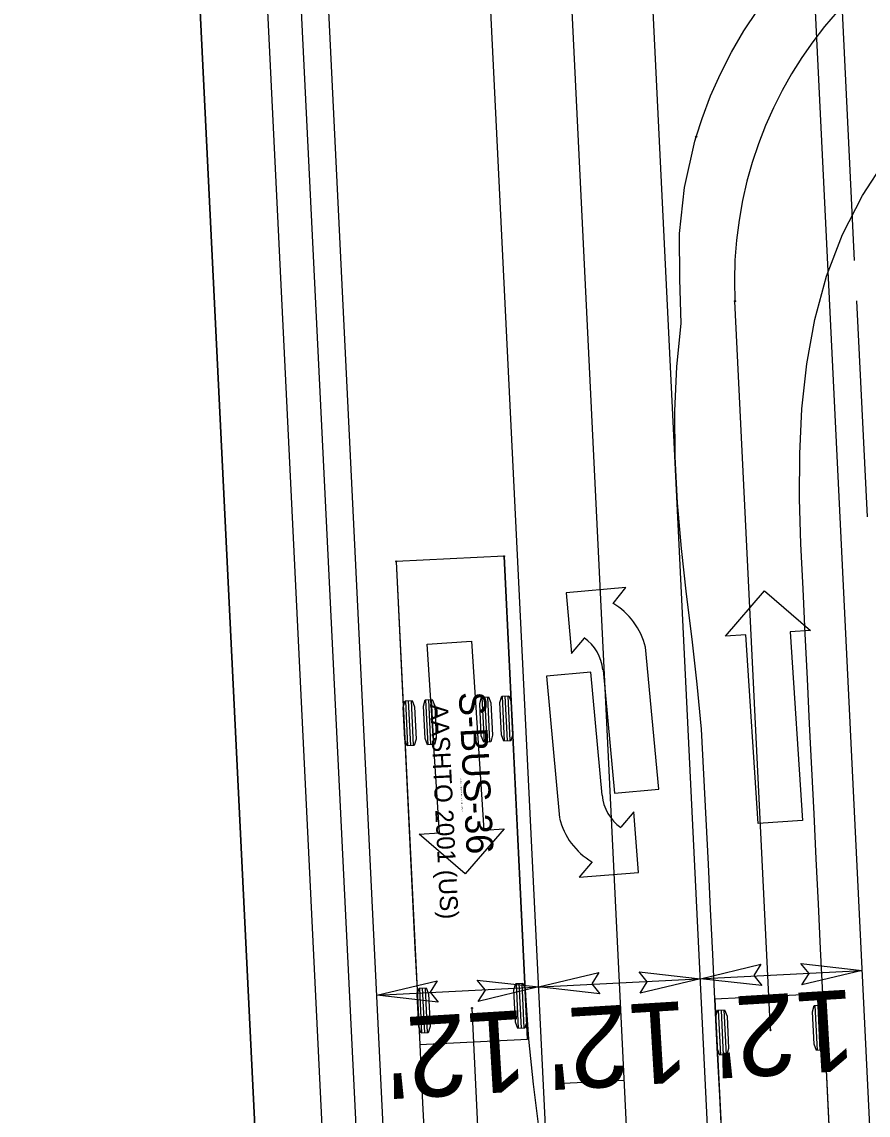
# Model space of a CAD drawing. Extents: x 2367848 to 2369479, y 800728 to 808616.
# Drawn here: x 2368775.2 to 2368837.9, y 804125 to 804206 of the extents above; entities that cross this region are included whole.
import ezdxf

# ---------------------------------------------------------------- set-up
doc = ezdxf.new("R2010")
doc.units = 0
for name, color, linetype in [('Prop AutoTurn Projected Path', 7, 'Continuous'), ('Prop AutoTurn Simulation', 7, 'Continuous'), ('Prop Conc 2ft 6in Curb and Gutter', 7, 'Continuous'), ('Prop Conc 4in Sidewalk', 7, 'Continuous'), ('Prop Conc Drive Radius Type', 7, 'Continuous'), ('Prop Dimension', 7, 'Continuous'), ('Prop EOT', 7, 'Continuous'), ('Prop Horizontal Alignment', 7, 'Continuous'), ('Prop Horizontal Alignment Tick Small', 7, 'Continuous'), ('Prop Lane Arrow CELL', 7, 'Continuous'), ('Prop Lane Lines', 7, 'Continuous'), ('Prop Shade Light', 7, 'Continuous'), ('Prop Terminator CELL', 7, 'Continuous')]:
    doc.layers.add(name, color=color, linetype=linetype)

msp = doc.modelspace()

# ---------------------------------------------------------------- linework, layer by layer
at = {"layer": 'Prop AutoTurn Projected Path'}
for p, q in [((2368830.646, 804131.326), (2368828.009, 804185.308)), ((2368810.142, 804100.159), (2368808.539, 804132.964))]:
    msp.add_line(p, q, dxfattribs=at)
msp.add_arc((2368857.973, 804186.772), 30, 93.79587, 182.79655, dxfattribs=at)
at = {"layer": 'Prop AutoTurn Simulation'}
for p, q in [((2368810.91, 804166.419), (2368802.919, 804166.029)), ((2368802.919, 804166.029), (2368804.666, 804130.272)), ((2368812.657, 804130.662), (2368810.91, 804166.419)), ((2368810.952, 804152.738), (2368810.79, 804156.068)), ((2368811.161, 804152.749), (2368810.998, 804156.078)), ((2368811.369, 804152.759), (2368811.206, 804156.088)), ((2368803.794, 804152.389), (2368803.632, 804155.718)), ((2368804.002, 804152.399), (2368803.84, 804155.728)), ((2368804.211, 804152.409), (2368804.048, 804155.738)), ((2368805.293, 804152.462), (2368805.13, 804155.791)), ((2368805.501, 804152.472), (2368805.338, 804155.801)), ((2368805.709, 804152.482), (2368805.546, 804155.812)), ((2368809.454, 804152.665), (2368809.292, 804155.995)), ((2368809.662, 804152.675), (2368809.5, 804156.005)), ((2368809.87, 804152.686), (2368809.708, 804156.015)), ((2368804.834, 804131.114), (2368804.671, 804134.443)), ((2368805.042, 804131.124), (2368804.879, 804134.454)), ((2368805.25, 804131.134), (2368805.087, 804134.464)), ((2368811.992, 804131.464), (2368811.829, 804134.793)), ((2368812.2, 804131.474), (2368812.037, 804134.803)), ((2368812.408, 804131.484), (2368812.245, 804134.813)), ((2368834.519, 804134.018), (2368826.528, 804133.628)), ((2368826.528, 804133.628), (2368828.275, 804097.871)), ((2368826.528, 804133.628), (2368826.528, 804133.628)), ((2368836.266, 804098.261), (2368834.519, 804134.018)), ((2368826.777, 804132.806), (2368826.94, 804129.476)), ((2368826.985, 804132.816), (2368827.148, 804129.487)), ((2368827.193, 804132.826), (2368827.356, 804129.497)), ((2368833.935, 804133.156), (2368834.098, 804129.826)), ((2368834.143, 804133.166), (2368834.306, 804129.836)), ((2368834.351, 804133.176), (2368834.514, 804129.846)), ((2368804.666, 804130.272), (2368812.657, 804130.662)), ((2368812.657, 804130.662), (2368812.657, 804130.662))]:
    msp.add_line(p, q, dxfattribs=at)
for points in [[(2368825.139, 804197.483), (2368825.576, 804198.832), (2368826.21, 804200.499), (2368826.94, 804202.139), (2368827.763, 804203.745), (2368828.678, 804205.313), (2368829.683, 804206.836)], [(2368827.052, 804122.901), (2368826.878, 804126.477), (2368826.703, 804130.052), (2368826.528, 804133.628), (2368826.528, 804133.628), (2368826.366, 804136.96), (2368826.203, 804140.292), (2368826.04, 804143.625), (2368825.877, 804146.957), (2368825.715, 804150.289), (2368825.528, 804153.62), (2368825.206, 804156.947), (2368824.839, 804160.277), (2368824.423, 804163.621), (2368824.041, 804166.987), (2368823.744, 804170.377), (2368823.574, 804173.778), (2368823.56, 804177.158), (2368823.712, 804180.468), (2368824.015, 804183.646), (2368823.924, 804186.944), (2368823.893, 804190.313), (2368824.264, 804193.732), (2368825.039, 804197.144), (2368825.139, 804197.483)], [(2368835.043, 804123.291), (2368834.868, 804126.867), (2368834.694, 804130.443), (2368834.519, 804134.018), (2368834.519, 804134.018), (2368834.519, 804134.018), (2368834.356, 804137.351), (2368834.193, 804140.683), (2368834.031, 804144.015), (2368833.868, 804147.347), (2368833.705, 804150.679), (2368833.542, 804154.012), (2368833.379, 804157.344), (2368833.217, 804160.676), (2368833.054, 804164.008), (2368832.9, 804167.341), (2368832.8, 804170.676), (2368832.806, 804174.011), (2368832.966, 804177.343), (2368833.324, 804180.658), (2368833.923, 804183.937), (2368834.8, 804187.152), (2368835.979, 804190.255), (2368837.443, 804193.139), (2368839.166, 804195.756)], [(2368802.919, 804166.029), (2368803.094, 804162.453), (2368803.269, 804158.877), (2368803.443, 804155.302), (2368803.618, 804151.726), (2368803.793, 804148.15), (2368803.967, 804144.575), (2368804.142, 804140.999), (2368804.317, 804137.423), (2368804.491, 804133.847), (2368804.666, 804130.272), (2368804.666, 804130.272), (2368804.666, 804130.272), (2368804.83, 804126.924), (2368804.993, 804123.577)], [(2368810.91, 804166.419), (2368811.085, 804162.844), (2368811.259, 804159.268), (2368811.434, 804155.692), (2368811.609, 804152.116), (2368811.783, 804148.541), (2368811.958, 804144.965), (2368812.133, 804141.389), (2368812.307, 804137.813), (2368812.482, 804134.238), (2368812.714, 804130.665), (2368812.714, 804130.665), (2368813.066, 804127.323), (2368813.48, 804123.974)]]:
    msp.add_lwpolyline(points, dxfattribs=at)
for points in [[(2368811.42, 804152.761), (2368810.901, 804152.736), (2368810.722, 804153.194), (2368810.605, 804155.591), (2368810.738, 804156.065), (2368811.258, 804156.091), (2368811.437, 804155.632), (2368811.554, 804153.235)], [(2368804.262, 804152.412), (2368803.743, 804152.386), (2368803.563, 804152.845), (2368803.446, 804155.242), (2368803.58, 804155.716), (2368804.099, 804155.741), (2368804.279, 804155.282), (2368804.396, 804152.885)], [(2368805.76, 804152.485), (2368805.241, 804152.459), (2368805.062, 804152.918), (2368804.945, 804155.315), (2368805.078, 804155.789), (2368805.598, 804155.814), (2368805.777, 804155.356), (2368805.894, 804152.959)], [(2368809.922, 804152.688), (2368809.403, 804152.663), (2368809.223, 804153.121), (2368809.106, 804155.518), (2368809.24, 804155.992), (2368809.759, 804156.017), (2368809.939, 804155.559), (2368810.056, 804153.162)], [(2368805.301, 804131.137), (2368804.782, 804131.112), (2368804.603, 804131.57), (2368804.486, 804133.967), (2368804.619, 804134.441), (2368805.139, 804134.466), (2368805.318, 804134.008), (2368805.435, 804131.611)], [(2368812.459, 804131.487), (2368811.94, 804131.461), (2368811.761, 804131.92), (2368811.644, 804134.317), (2368811.777, 804134.791), (2368812.297, 804134.816), (2368812.476, 804134.358), (2368812.593, 804131.96)], [(2368826.726, 804132.803), (2368827.245, 804132.829), (2368827.424, 804132.37), (2368827.541, 804129.973), (2368827.408, 804129.499), (2368826.888, 804129.474), (2368826.709, 804129.932), (2368826.592, 804132.33)], [(2368833.884, 804133.153), (2368834.403, 804133.178), (2368834.582, 804132.72), (2368834.699, 804130.323), (2368834.566, 804129.849), (2368834.046, 804129.824), (2368833.867, 804130.282), (2368833.75, 804132.679)]]:
    msp.add_lwpolyline(points, close=True, dxfattribs=at)
for centre in [(2368825.139, 804197.483), (2368825.139, 804197.483), (2368828.009, 804185.308), (2368828.009, 804185.308), (2368802.919, 804166.029), (2368810.91, 804166.419), (2368808.539, 804132.964), (2368830.646, 804131.326)]:
    msp.add_circle(centre, 0.0417, dxfattribs=at)
at = {"layer": 'Prop Conc 2ft 6in Curb and Gutter'}
for p, q in [((2368800.464, 804113.821), (2368788.232, 804364.218)), ((2368836.873, 804188.324), (2368835.891, 804208.441))]:
    msp.add_line(p, q, dxfattribs=at)
at = {"layer": 'Prop Conc 4in Sidewalk'}
for p, q in [((2368792.973, 804113.455), (2368780.555, 804367.675)), ((2368797.967, 804113.699), (2368785.591, 804367.049))]:
    msp.add_line(p, q, dxfattribs=at)
at = {"layer": 'Prop Conc Drive Radius Type'}
msp.add_line((2368837.019, 804185.327), (2368837.799, 804169.346), dxfattribs=at)
at = {"layer": 'Prop Dimension'}
msp.add_line((2368801.485, 804133.911), (2368837.437, 804135.757), dxfattribs=at)
at = {"layer": 'Prop EOT'}
for p, q in [((2368802.461, 804113.918), (2368775.205, 804671.908)), ((2368856.007, 803755.598), (2368830.838, 804270.858))]:
    msp.add_line(p, q, dxfattribs=at)
at = {"layer": 'Prop Horizontal Alignment'}
msp.add_line((2368838.029, 803754.72), (2368793.183, 804672.786), dxfattribs=at)
at = {"layer": 'Prop Horizontal Alignment Tick Small'}
msp.add_line((2368819.814, 804127.607), (2368814.82, 804127.363), dxfattribs=at)
msp.add_line((2368819.814, 804127.607), (2368814.82, 804127.363), dxfattribs=at)
at = {"layer": 'Prop Lane Arrow CELL'}
for p, q in [((2368819.934, 804164.113), (2368815.503, 804163.705)), ((2368815.503, 804163.705), (2368815.915, 804159.224)), ((2368818.989, 804162.921), (2368819.934, 804164.113)), ((2368827.319, 804160.503), (2368830.208, 804163.848)), ((2368830.208, 804163.848), (2368833.606, 804160.913)), ((2368805.214, 804159.906), (2368808.507, 804160.12)), ((2368808.507, 804160.12), (2368809.417, 804146.15)), ((2368815.915, 804159.224), (2368816.865, 804160.365)), ((2368828.816, 804160.6), (2368827.319, 804160.503)), ((2368829.727, 804146.63), (2368828.816, 804160.6)), ((2368833.606, 804160.913), (2368832.109, 804160.815)), ((2368832.109, 804160.815), (2368833.02, 804146.845)), ((2368806.124, 804145.935), (2368805.214, 804159.906)), ((2368822.364, 804149.172), (2368821.397, 804159.678)), ((2368817.347, 804157.849), (2368814.061, 804157.547)), ((2368818.186, 804148.738), (2368817.347, 804157.849)), ((2368818.239, 804157.981), (2368819.078, 804148.87)), ((2368814.061, 804157.547), (2368815.028, 804147.041)), ((2368819.078, 804148.87), (2368822.364, 804149.172)), ((2368820.51, 804147.495), (2368819.56, 804146.354)), ((2368820.872, 804143.01), (2368820.51, 804147.495)), ((2368833.02, 804146.845), (2368829.727, 804146.63)), ((2368804.628, 804145.838), (2368806.124, 804145.935)), ((2368808.026, 804142.903), (2368804.628, 804145.838)), ((2368810.914, 804146.248), (2368808.026, 804142.903)), ((2368809.417, 804146.15), (2368810.914, 804146.248)), ((2368817.436, 804143.798), (2368816.486, 804142.656)), ((2368816.486, 804142.656), (2368820.872, 804143.01))]:
    msp.add_line(p, q, dxfattribs=at)
for centre, radius, start, end in [((2368816.286, 804158.425), 5.253, 13.93509, 59.24678), ((2368814.964, 804157.703), 3.275, 5.25902, 54.91719), ((2368821.431, 804149.026), 3.275, 185.25902, 234.91719), ((2368820.109, 804148.304), 5.253, 193.93509, 239.24678)]:
    msp.add_arc(centre, radius, start, end, dxfattribs=at)
at = {"layer": 'Prop Lane Lines'}
for p, q in [((2368844.022, 803755.012), (2368799.176, 804673.079)), ((2368832.036, 803754.427), (2368787.191, 804672.493))]:
    msp.add_line(p, q, dxfattribs=at)
at = {"layer": 'Prop Shade Light'}
for p, q in [((2368780.595, 804366.849), (2368792.973, 804113.455)), ((2368797.967, 804113.699), (2368785.591, 804367.049))]:
    msp.add_line(p, q, dxfattribs=at)
at = {"layer": 'Prop Terminator CELL'}
for points in [[(2368829.992, 804134.64), (2368825.453, 804135.142), (2368829.922, 804136.213), (2368829.396, 804135.38)], [(2368832.899, 804136.26), (2368837.437, 804135.757), (2368832.969, 804134.686), (2368833.495, 804135.519)], [(2368808.93, 804135.028), (2368813.469, 804134.526), (2368809.001, 804133.455), (2368809.526, 804134.288)], [(2368818.008, 804134.024), (2368813.469, 804134.526), (2368817.938, 804135.598), (2368817.412, 804134.765)], [(2368820.915, 804135.644), (2368825.453, 804135.142), (2368820.985, 804134.07), (2368821.51, 804134.904)], [(2368806.023, 804133.409), (2368801.485, 804133.911), (2368805.953, 804134.982), (2368805.428, 804134.149)]]:
    msp.add_lwpolyline(points, close=True, dxfattribs=at)

# ---------------------------------------------------------------- texts
at = {"layer": 'Prop AutoTurn Simulation'}
for s, height, p in [('S-BUS-36', 2, (2368807.558, 804156.344)), ('AASHTO 2001 (US)', 1.33333, (2368805.432, 804155.453)), ('(c) 2014 Transoft Solutions, Inc. All rights reserved.', 0.08, (2368807.669, 804149.972))]:
    msp.add_text(s, height=height, rotation=272.79655, dxfattribs=at).set_placement(p)
at = {"layer": 'Prop Dimension'}
for p in [(2368836.772, 804134.354), (2368824.39, 804133.494), (2368812.443, 804132.828)]:
    msp.add_text("12'", height=6, rotation=183.45855, dxfattribs=at).set_placement(p)

doc.saveas('drawing.dxf')
